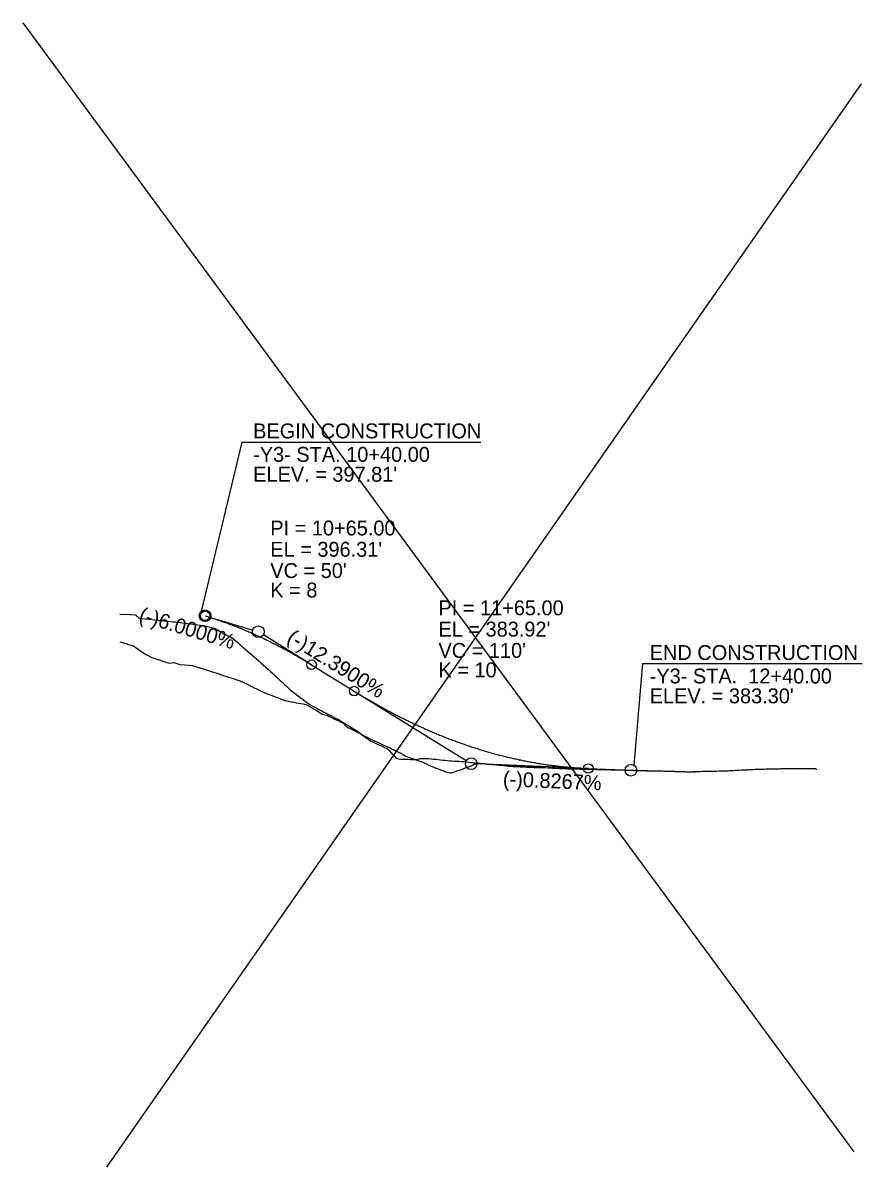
# Model space of a CAD drawing. Extents: x 1625686 to 1640492, y 1161393 to 1175642.
# Drawn here: x 1631145 to 1631540, y 1164721 to 1165258 of the extents above; entities that cross this region are included whole.
import ezdxf

# ---------------------------------------------------------------- set-up
doc = ezdxf.new("R2010")
doc.units = 0
for name, color, linetype in [('Exist Vertical Profile Ground Line', 7, 'Continuous'), ('Prop Vertical Profile Curve Label', 7, 'Continuous'), ('Prop Vertical Profile Grade', 7, 'Continuous'), ('Prop Vertical Profile Grade Label', 7, 'Continuous'), ('Prop VPI Label', 7, 'Continuous'), ('Scratch_Level_1', 7, 'Continuous'), ('Scratch_Level_3', 7, 'Continuous')]:
    doc.layers.add(name, color=color, linetype=linetype)

msp = doc.modelspace()

# ---------------------------------------------------------------- linework, layer by layer
at = {"layer": 'Exist Vertical Profile Ground Line'}
msp.add_lwpolyline([(1631191.04, 1164980.42), (1631195.96, 1164980.3), (1631198.27, 1164980.2), (1631200.18, 1164978.4), (1631201.29, 1164978.45), (1631216.18, 1164976.93), (1631216.75, 1164976.86), (1631217.11, 1164976.82), (1631231, 1164974.96), (1631235.41, 1164973.97), (1631240.72, 1164970.82), (1631241.99, 1164970.19), (1631243.08, 1164969.65), (1631243.96, 1164969.22), (1631245.27, 1164968.07), (1631246.37, 1164967.11), (1631247.46, 1164966.15), (1631248.56, 1164965.19), (1631249.65, 1164964.23), (1631250.75, 1164963.28), (1631251.84, 1164962.32), (1631253.01, 1164961.31), (1631254.03, 1164960.41), (1631255.12, 1164959.45), (1631256.22, 1164958.49), (1631257.31, 1164957.53), (1631258.41, 1164956.58), (1631259.5, 1164955.61), (1631260.6, 1164954.58), (1631261.69, 1164953.56), (1631262.79, 1164952.55), (1631263.88, 1164951.53), (1631264.98, 1164950.52), (1631266.07, 1164949.51), (1631267.17, 1164948.5), (1631268.26, 1164947.49), (1631269.36, 1164946.49), (1631270.45, 1164945.49), (1631271.55, 1164944.48), (1631272.64, 1164943.65), (1631273.74, 1164942.82), (1631274.83, 1164941.99), (1631275.93, 1164941.16), (1631277.02, 1164940.33), (1631278.11, 1164939.51), (1631279.21, 1164938.69), (1631280.3, 1164937.88), (1631281.4, 1164937.31), (1631282.49, 1164936.74), (1631283.59, 1164936.18), (1631284.68, 1164935.62), (1631285.78, 1164935.05), (1631286.87, 1164934.49), (1631287.97, 1164933.93), (1631289.06, 1164933.37), (1631290.16, 1164932.82), (1631291.25, 1164932.26), (1631292.35, 1164931.7), (1631293.44, 1164931.14), (1631294.54, 1164930.48), (1631295.63, 1164929.82), (1631296.73, 1164929.15), (1631297.82, 1164928.49), (1631298.91, 1164927.82), (1631300.01, 1164927.15), (1631301.1, 1164926.48), (1631302.2, 1164925.8), (1631303.29, 1164924.99), (1631304.39, 1164924.17), (1631305.48, 1164923.36), (1631306.58, 1164922.54), (1631307.67, 1164921.73), (1631308.76, 1164920.93), (1631309.86, 1164920.44), (1631310.95, 1164919.94), (1631312.05, 1164919.44), (1631313.14, 1164918.94), (1631314.24, 1164918.43), (1631315.33, 1164917.92), (1631316.71, 1164917.28), (1631317.52, 1164916.41), (1631318.62, 1164915.22), (1631319.71, 1164914.04), (1631320.8, 1164912.89), (1631321.9, 1164912.59), (1631322.99, 1164912.34), (1631324.09, 1164912.33), (1631325.18, 1164912.31), (1631326.28, 1164912.3), (1631327.37, 1164912.28), (1631328.47, 1164912.26), (1631329.56, 1164912.26), (1631330.65, 1164912.41), (1631331.75, 1164912.55), (1631332.18, 1164912.61), (1631332.84, 1164912.62), (1631333.94, 1164912.64), (1631335.03, 1164912.66), (1631335.57, 1164912.67), (1631336.13, 1164912.61), (1631337.22, 1164912.51), (1631338.32, 1164912.4), (1631339.41, 1164912.3), (1631340.51, 1164912.19), (1631341.6, 1164912.08), (1631342.69, 1164911.97), (1631343.79, 1164911.86), (1631344.88, 1164911.75), (1631345.98, 1164911.64), (1631347.07, 1164911.53), (1631348.17, 1164911.48), (1631349.26, 1164911.42), (1631350.36, 1164911.37), (1631351.45, 1164911.31), (1631352.55, 1164911.25), (1631353.64, 1164911.18), (1631354.73, 1164911), (1631355.83, 1164910.83), (1631356.49, 1164910.73), (1631356.92, 1164910.69), (1631358.02, 1164910.59), (1631359.11, 1164910.49), (1631360.22, 1164910.39), (1631361.3, 1164910.29), (1631362.4, 1164910.19), (1631363.49, 1164910.09), (1631364.58, 1164909.99), (1631365.01, 1164909.95), (1631365.68, 1164909.9), (1631366.77, 1164909.8), (1631367.87, 1164909.71), (1631368.96, 1164909.61), (1631370.06, 1164909.52), (1631371.15, 1164909.42), (1631372.25, 1164909.32), (1631372.85, 1164909.27), (1631373.41, 1164909.32), (1631374.44, 1164909.4), (1631375.69, 1164909.48), (1631376.62, 1164909.38), (1631377.72, 1164909.27), (1631378.81, 1164909.17), (1631379.91, 1164909.11), (1631381, 1164909.05), (1631382.1, 1164908.99), (1631382.74, 1164908.95), (1631383.19, 1164908.92), (1631384.29, 1164908.86), (1631385.38, 1164908.79), (1631386.47, 1164908.72), (1631387.57, 1164908.65), (1631388.66, 1164908.58), (1631389.76, 1164908.51), (1631390.85, 1164908.44), (1631391.95, 1164908.37), (1631393.04, 1164908.3), (1631394.14, 1164908.22), (1631395.23, 1164908.15), (1631396.33, 1164908.08), (1631397.42, 1164908), (1631398.2, 1164907.95), (1631398.51, 1164907.95), (1631399.61, 1164907.93), (1631400.7, 1164907.92), (1631401.8, 1164907.9), (1631402.95, 1164907.89), (1631403.99, 1164907.85), (1631405.08, 1164907.8), (1631406.18, 1164907.76), (1631407.42, 1164907.71), (1631408.37, 1164907.7), (1631409.46, 1164907.69), (1631410.55, 1164907.68), (1631411.65, 1164907.67), (1631412.74, 1164907.65), (1631413.84, 1164907.64), (1631414.93, 1164907.62), (1631416.03, 1164907.6), (1631417.12, 1164907.58), (1631418.22, 1164907.56), (1631419.31, 1164907.54), (1631420.4, 1164907.52), (1631421.5, 1164907.49), (1631422.59, 1164907.47), (1631423.69, 1164907.44), (1631424.78, 1164907.41), (1631425.88, 1164907.38), (1631426.97, 1164907.35), (1631428.7, 1164907.3), (1631433.57, 1164907.19), (1631444.01, 1164906.87), (1631444.87, 1164906.85), (1631445.72, 1164906.82), (1631446.58, 1164906.79), (1631447.44, 1164906.77), (1631448.3, 1164906.74), (1631449.15, 1164906.71), (1631450.01, 1164906.69), (1631450.87, 1164906.66), (1631451.73, 1164906.63), (1631452.59, 1164906.6), (1631453.67, 1164906.57), (1631454.3, 1164906.56), (1631455.16, 1164906.51), (1631456.02, 1164906.51), (1631456.49, 1164906.51), (1631456.87, 1164906.49), (1631457.73, 1164906.48), (1631458.59, 1164906.46), (1631459.45, 1164906.45), (1631460.31, 1164906.45), (1631460.62, 1164906.45), (1631461.16, 1164906.49), (1631462.02, 1164906.56), (1631462.88, 1164906.6), (1631463.74, 1164906.64), (1631464.63, 1164906.68), (1631465.45, 1164906.68), (1631466.31, 1164906.67), (1631467.18, 1164906.66), (1631468.03, 1164906.7), (1631468.5, 1164906.72), (1631468.88, 1164906.73), (1631469.79, 1164906.74), (1631470.6, 1164906.77), (1631471.46, 1164906.8), (1631472.55, 1164906.83), (1631473.26, 1164906.85), (1631474.03, 1164906.85), (1631474.95, 1164906.86), (1631475.75, 1164906.88), (1631476.73, 1164906.91), (1631477.51, 1164906.98), (1631478.32, 1164907.04), (1631478.87, 1164907.08), (1631479.18, 1164907.11), (1631480.05, 1164907.19), (1631481.04, 1164907.22), (1631481.75, 1164907.25), (1631482.61, 1164907.3), (1631483.47, 1164907.32), (1631484.6, 1164907.36), (1631485.18, 1164907.38), (1631486.04, 1164907.42), (1631486.9, 1164907.46), (1631487.76, 1164907.5), (1631488.61, 1164907.55), (1631489.47, 1164907.6), (1631490.33, 1164907.64), (1631491.19, 1164907.67), (1631492.05, 1164907.69), (1631492.9, 1164907.72), (1631493.76, 1164907.74), (1631494.62, 1164907.76), (1631495.48, 1164907.78), (1631496.33, 1164907.8), (1631497.19, 1164907.81), (1631497.62, 1164907.82), (1631498.05, 1164907.83), (1631498.91, 1164907.85), (1631499.77, 1164907.87), (1631500.12, 1164907.88), (1631500.76, 1164907.89), (1631501.48, 1164907.91), (1631502.62, 1164907.92), (1631503.2, 1164907.93), (1631504.06, 1164907.93), (1631505.13, 1164907.94), (1631505.77, 1164907.94), (1631506.63, 1164907.94), (1631507.65, 1164907.94), (1631508.34, 1164907.95), (1631509.3, 1164907.96), (1631510.18, 1164907.98), (1631510.92, 1164908), (1631511.39, 1164908.01), (1631511.78, 1164908.01), (1631512.71, 1164908.02), (1631513.49, 1164908.02), (1631514.53, 1164908.03), (1631515.26, 1164908.03), (1631516.06, 1164908.03), (1631516.92, 1164908.04), (1631517.83, 1164908.04)], dxfattribs=at)
at = {"layer": 'Prop Vertical Profile Curve Label'}
for centre in [(1631231.04, 1164979.72), (1631281.04, 1164956.74), (1631301.04, 1164944.35), (1631411.04, 1164908)]:
    msp.add_circle(centre, 2.25, dxfattribs=at)
at = {"layer": 'Prop Vertical Profile Grade'}
for p, q in [((1631281.04, 1164956.74), (1631301.04, 1164944.35)), ((1631411.04, 1164908), (1631431.04, 1164907.17))]:
    msp.add_line(p, q, dxfattribs=at)
for points in [[(1631231.04, 1164979.72), (1631232.04, 1164979.42), (1631233.04, 1164979.11), (1631234.04, 1164978.8), (1631235.04, 1164978.47), (1631236.04, 1164978.14), (1631237.04, 1164977.81), (1631238.04, 1164977.47), (1631239.04, 1164977.12), (1631240.04, 1164976.77), (1631241.04, 1164976.4), (1631242.04, 1164976.04), (1631243.04, 1164975.66), (1631244.04, 1164975.28), (1631245.04, 1164974.9), (1631246.04, 1164974.51), (1631247.04, 1164974.11), (1631248.04, 1164973.7), (1631249.04, 1164973.29), (1631250.04, 1164972.87), (1631251.04, 1164972.45), (1631252.04, 1164972.02), (1631253.04, 1164971.58), (1631254.04, 1164971.13), (1631255.04, 1164970.68), (1631256.04, 1164970.23), (1631257.04, 1164969.76), (1631258.04, 1164969.3), (1631259.04, 1164968.82), (1631260.04, 1164968.34), (1631261.04, 1164967.85), (1631262.04, 1164967.35), (1631263.04, 1164966.85), (1631264.04, 1164966.34), (1631265.04, 1164965.83), (1631266.04, 1164965.31), (1631267.04, 1164964.78), (1631268.04, 1164964.25), (1631269.04, 1164963.71), (1631270.04, 1164963.16), (1631271.04, 1164962.61), (1631272.04, 1164962.05), (1631273.04, 1164961.49), (1631274.04, 1164960.92), (1631275.04, 1164960.34), (1631276.04, 1164959.75), (1631277.04, 1164959.16), (1631278.04, 1164958.57), (1631279.04, 1164957.96), (1631280.04, 1164957.35), (1631281.04, 1164956.74)], [(1631301.04, 1164944.35), (1631303.24, 1164943), (1631305.44, 1164941.67), (1631307.64, 1164940.37), (1631309.84, 1164939.1), (1631312.04, 1164937.85), (1631314.24, 1164936.63), (1631316.44, 1164935.43), (1631318.64, 1164934.26), (1631320.84, 1164933.11), (1631323.04, 1164931.99), (1631325.24, 1164930.89), (1631327.44, 1164929.82), (1631329.64, 1164928.78), (1631331.84, 1164927.76), (1631334.04, 1164926.77), (1631336.24, 1164925.8), (1631338.44, 1164924.85), (1631340.64, 1164923.94), (1631342.84, 1164923.04), (1631345.04, 1164922.18), (1631347.24, 1164921.34), (1631349.44, 1164920.52), (1631351.64, 1164919.73), (1631353.84, 1164918.96), (1631356.04, 1164918.22), (1631358.24, 1164917.51), (1631360.44, 1164916.82), (1631362.64, 1164916.16), (1631364.84, 1164915.52), (1631367.04, 1164914.91), (1631369.24, 1164914.32), (1631371.44, 1164913.76), (1631373.64, 1164913.22), (1631375.84, 1164912.71), (1631378.04, 1164912.23), (1631380.24, 1164911.77), (1631382.44, 1164911.33), (1631384.64, 1164910.92), (1631386.84, 1164910.54), (1631389.04, 1164910.18), (1631391.24, 1164909.85), (1631393.44, 1164909.54), (1631395.64, 1164909.26), (1631397.84, 1164909), (1631400.04, 1164908.77), (1631402.24, 1164908.57), (1631404.44, 1164908.39), (1631406.64, 1164908.23), (1631408.84, 1164908.1), (1631411.04, 1164908)]]:
    msp.add_spline(points, degree=3, dxfattribs=at)
at = {"layer": 'Prop Vertical Profile Grade Label'}
for p, q in [((1631248.27, 1165061.37), (1631229.23, 1164981.79)), ((1631248.27, 1165061.37), (1631360.47, 1165061.37)), ((1631436.54, 1164957.25), (1631432.4, 1164909.56)), ((1631436.54, 1164957.25), (1631539.64, 1164957.25))]:
    msp.add_line(p, q, dxfattribs=at)
at = {"layer": 'Prop VPI Label'}
for p, q in [((1631231.04, 1164979.72), (1631253.4, 1164973.01)), ((1631281.04, 1164956.74), (1631258.38, 1164970.78)), ((1631301.04, 1164944.35), (1631353.7, 1164911.72)), ((1631411.04, 1164908), (1631358.79, 1164910.16))]:
    msp.add_line(p, q, dxfattribs=at)
for centre in [(1631231.04, 1164979.72), (1631256.04, 1164972.22), (1631356.04, 1164910.27), (1631431.04, 1164907.17)]:
    msp.add_circle(centre, 2.75, dxfattribs=at)
at = {"layer": 'Scratch_Level_1'}
for points in [[(1631191.04, 1164967.45), (1631193.89, 1164966.67), (1631194.55, 1164966.46), (1631197.41, 1164965.58), (1631198.67, 1164964.74), (1631203.13, 1164961.59), (1631203.89, 1164961.21), (1631205.99, 1164960.19), (1631208.4, 1164959.35), (1631213.07, 1164957.76), (1631214.1, 1164957.53), (1631216.28, 1164957.76), (1631219.15, 1164956.9), (1631223.6, 1164956.47), (1631224.91, 1164956.33), (1631225.36, 1164956.23), (1631226.08, 1164956.02), (1631232.62, 1164953.96), (1631233.8, 1164953.61), (1631236, 1164952.86), (1631239.24, 1164951.82), (1631241.99, 1164950.93), (1631243.08, 1164950.58), (1631244.18, 1164950.22), (1631245.44, 1164949.81), (1631246.37, 1164949.49), (1631247.46, 1164949.11), (1631248.03, 1164948.92), (1631248.56, 1164948.66), (1631249.65, 1164948.12), (1631250.75, 1164947.58), (1631251.84, 1164947.03), (1631252.22, 1164946.84), (1631252.94, 1164946.49), (1631254.03, 1164945.95), (1631255.12, 1164945.41), (1631256.22, 1164944.87), (1631257.31, 1164944.32), (1631258.41, 1164943.79), (1631259.5, 1164943.38), (1631260.6, 1164942.97), (1631261.69, 1164942.55), (1631262.79, 1164942.13), (1631263.88, 1164941.72), (1631264.62, 1164941.43), (1631264.98, 1164941.29), (1631266.07, 1164940.84), (1631267.17, 1164940.4), (1631268.37, 1164939.9), (1631269.36, 1164939.72), (1631270.45, 1164939.52), (1631271.55, 1164939.32), (1631272.64, 1164939.12), (1631273.74, 1164938.91), (1631274.83, 1164938.71), (1631275.93, 1164938.5), (1631277.02, 1164938.31), (1631278.41, 1164938.07), (1631279.21, 1164937.6), (1631280.3, 1164936.95), (1631281.4, 1164936.31), (1631282.49, 1164935.67), (1631283.59, 1164935.02), (1631284.68, 1164934.38), (1631285.78, 1164933.73), (1631286.09, 1164933.54), (1631286.87, 1164933.34), (1631287.97, 1164933.05), (1631288.41, 1164932.93), (1631289.06, 1164932.61), (1631290.16, 1164932.08), (1631291.25, 1164931.55), (1631292.35, 1164931.02), (1631293.44, 1164930.5), (1631294.54, 1164929.97), (1631295.74, 1164929.39), (1631296.73, 1164928.56), (1631297.82, 1164927.63), (1631298.46, 1164927.08), (1631298.91, 1164926.88), (1631300.01, 1164926.41), (1631300.32, 1164926.27), (1631301.1, 1164925.86), (1631302.2, 1164925.28), (1631303.29, 1164924.7), (1631304.39, 1164924.12), (1631305.48, 1164923.54), (1631306.58, 1164922.97), (1631307.67, 1164922.39), (1631308.29, 1164922.07), (1631308.84, 1164921.81), (1631309.86, 1164921.33), (1631310.95, 1164920.82), (1631312.05, 1164920.31), (1631313.14, 1164919.81), (1631314.24, 1164919.32), (1631315.59, 1164918.71), (1631316.43, 1164918.31), (1631317.52, 1164917.79), (1631318.62, 1164917.26), (1631319.71, 1164916.74)], [(1631319.71, 1164916.74), (1631320.8, 1164916.22), (1631321.9, 1164915.69), (1631322.99, 1164915.15), (1631324.09, 1164914.49), (1631325.29, 1164913.77), (1631326.28, 1164913.42), (1631327.37, 1164913.03), (1631328.47, 1164912.65), (1631329.56, 1164912.26), (1631330.65, 1164911.87), (1631331.75, 1164911.48), (1631332.84, 1164911.1), (1631333.39, 1164910.93), (1631333.94, 1164910.65), (1631335.03, 1164910.11), (1631336.13, 1164909.58), (1631337.22, 1164909.05), (1631338.32, 1164908.63), (1631339.41, 1164908.21), (1631340.51, 1164907.8), (1631341.6, 1164907.38), (1631342.69, 1164906.97), (1631343.03, 1164906.85), (1631343.93, 1164906.47), (1631344.45, 1164906.32), (1631344.88, 1164906.24), (1631346.12, 1164906), (1631346.6, 1164905.91), (1631347.07, 1164906.08), (1631348.17, 1164906.47), (1631349.26, 1164906.84), (1631350.36, 1164907.2), (1631351, 1164907.41), (1631351.45, 1164907.58), (1631352.55, 1164907.99), (1631353.64, 1164908.39), (1631354.73, 1164908.77), (1631355.26, 1164908.95), (1631355.99, 1164909.21), (1631356.92, 1164909.69), (1631358.02, 1164910.24), (1631358.79, 1164910.62), (1631359.11, 1164910.59), (1631360.21, 1164910.48), (1631361.3, 1164910.37), (1631362.4, 1164910.26), (1631363.49, 1164910.14), (1631364.58, 1164910.03), (1631365.68, 1164909.92), (1631366.9, 1164909.79), (1631367.87, 1164909.7), (1631368.96, 1164909.6), (1631370.06, 1164909.49), (1631371.15, 1164909.38), (1631372.25, 1164909.27), (1631372.74, 1164909.22), (1631373.34, 1164909.16), (1631374.06, 1164909.08), (1631374.44, 1164909.06), (1631375.17, 1164909.02), (1631375.53, 1164909), (1631376.62, 1164908.93), (1631377.3, 1164908.89), (1631377.72, 1164908.86), (1631378.98, 1164908.77), (1631379.91, 1164908.76), (1631381.24, 1164908.72), (1631382.1, 1164908.69), (1631382.77, 1164908.66), (1631383.19, 1164908.64), (1631383.82, 1164908.61), (1631384.29, 1164908.59), (1631385.63, 1164908.53), (1631386.47, 1164908.53), (1631387.65, 1164908.47), (1631388.66, 1164908.45), (1631389.03, 1164908.44), (1631389.76, 1164908.4), (1631390.85, 1164908.38), (1631391.95, 1164908.35), (1631393.04, 1164908.31), (1631394.29, 1164908.26), (1631395.23, 1164908.24), (1631395.7, 1164908.22), (1631396.33, 1164908.2), (1631396.95, 1164908.17), (1631397.42, 1164908.16), (1631398.51, 1164908.13), (1631399.08, 1164908.11), (1631399.62, 1164908.1), (1631400.7, 1164908.05), (1631401.4, 1164908.01), (1631401.8, 1164908.01), (1631402.31, 1164908), (1631402.89, 1164907.97), (1631403.31, 1164907.95), (1631403.99, 1164907.94), (1631405.22, 1164907.89), (1631405.68, 1164907.9), (1631406.18, 1164907.88)], [(1631406.18, 1164907.88), (1631407.27, 1164907.85), (1631407.75, 1164907.83), (1631408.37, 1164907.79), (1631409.01, 1164907.74), (1631409.46, 1164907.77), (1631410.55, 1164907.83), (1631410.89, 1164907.82), (1631411.68, 1164907.79), (1631412.76, 1164907.67), (1631413.29, 1164907.67), (1631413.84, 1164907.62), (1631414.62, 1164907.55), (1631414.93, 1164907.56), (1631416.09, 1164907.58), (1631416.48, 1164907.56), (1631417.21, 1164907.56), (1631418.22, 1164907.48), (1631418.92, 1164907.42), (1631419.31, 1164907.43), (1631420.4, 1164907.45), (1631420.99, 1164907.46), (1631421.78, 1164907.43), (1631422.59, 1164907.41), (1631423.69, 1164907.37), (1631424.78, 1164907.33), (1631425.88, 1164907.33), (1631427.6, 1164907.31), (1631429.29, 1164907.11), (1631430.54, 1164907.16), (1631432.03, 1164907.12), (1631432.93, 1164907.02), (1631433.47, 1164907.05), (1631434.74, 1164906.95), (1631436.8, 1164907.06), (1631438.38, 1164906.91), (1631439.35, 1164906.95), (1631440.19, 1164906.91), (1631441.57, 1164906.96), (1631442.28, 1164906.94), (1631443.43, 1164906.93), (1631444.01, 1164906.9), (1631444.87, 1164906.87), (1631445.21, 1164906.85), (1631445.72, 1164906.84), (1631446.58, 1164906.81), (1631447.48, 1164906.72), (1631448.3, 1164906.72), (1631449.32, 1164906.65), (1631450.01, 1164906.68), (1631450.94, 1164906.72), (1631451.73, 1164906.69), (1631452.59, 1164906.62), (1631453.03, 1164906.59), (1631453.73, 1164906.57), (1631454.3, 1164906.54), (1631455.16, 1164906.51), (1631456.02, 1164906.51), (1631456.49, 1164906.51), (1631456.87, 1164906.5), (1631457.73, 1164906.49), (1631458.59, 1164906.46), (1631459.45, 1164906.46), (1631460.41, 1164906.52), (1631461.16, 1164906.53), (1631462.02, 1164906.55), (1631462.56, 1164906.57), (1631462.88, 1164906.59), (1631463.74, 1164906.64), (1631464.63, 1164906.68), (1631465.45, 1164906.68), (1631466.31, 1164906.67), (1631467.18, 1164906.66), (1631468.03, 1164906.7), (1631468.5, 1164906.72), (1631468.88, 1164906.73), (1631469.79, 1164906.74), (1631470.6, 1164906.77), (1631471.46, 1164906.8), (1631472.55, 1164906.83), (1631473.25, 1164906.85), (1631474.03, 1164906.85), (1631474.95, 1164906.86), (1631475.75, 1164906.91), (1631476.6, 1164906.95), (1631477.51, 1164906.98), (1631478.32, 1164907.05), (1631478.65, 1164907.08), (1631479.18, 1164907.12), (1631480.05, 1164907.19), (1631481.04, 1164907.22), (1631481.75, 1164907.25), (1631482.61, 1164907.3), (1631483.47, 1164907.32), (1631484.33, 1164907.35), (1631485.18, 1164907.38), (1631485.49, 1164907.39), (1631486.04, 1164907.42), (1631486.9, 1164907.46), (1631487.78, 1164907.51), (1631488.61, 1164907.55)], [(1631488.61, 1164907.55), (1631489.47, 1164907.6), (1631490.33, 1164907.64), (1631491.19, 1164907.67), (1631492.05, 1164907.69), (1631492.9, 1164907.72), (1631493.76, 1164907.74), (1631494.62, 1164907.76), (1631495.48, 1164907.78), (1631496.33, 1164907.8), (1631497.19, 1164907.81), (1631497.74, 1164907.82), (1631498.05, 1164907.83), (1631498.91, 1164907.85), (1631499.77, 1164907.87), (1631500.15, 1164907.88), (1631500.76, 1164907.9), (1631501.48, 1164907.91), (1631502.76, 1164907.92), (1631503.2, 1164907.93), (1631504.06, 1164907.93), (1631505.13, 1164907.94), (1631505.77, 1164907.94), (1631506.63, 1164907.94), (1631507.65, 1164907.94), (1631508.4, 1164907.95), (1631509.2, 1164907.96), (1631510.18, 1164907.98), (1631510.92, 1164908), (1631511.39, 1164908.01), (1631511.78, 1164908.01), (1631512.71, 1164908.02), (1631513.49, 1164908.02), (1631514.53, 1164908.03), (1631515.26, 1164908.03), (1631516.06, 1164908.03), (1631516.92, 1164908.04), (1631517.83, 1164908.04), (1631518.11, 1164907.3)]]:
    msp.add_lwpolyline(points, dxfattribs=at)
at = {"layer": 'Scratch_Level_3'}
for p, q in [((1631145.43, 1165258.27), (1631535.82, 1164727.88)), ((1631184.83, 1164720.72), (1631539.41, 1165229.6))]:
    msp.add_line(p, q, dxfattribs=at)

# ---------------------------------------------------------------- texts
at = {"layer": 'Prop Vertical Profile Curve Label'}
for s, p in [("VC = 50'", (1631261.65, 1164997.47)), ('K = 8', (1631261.65, 1164988.33)), ("VC = 110'", (1631340.65, 1164959.96)), ('K = 10', (1631340.65, 1164950.81))]:
    msp.add_text(s, height=7, dxfattribs=at).set_placement(p)
at = {"layer": 'Prop Vertical Profile Grade Label'}
for s, rotation, p in [('(-)6.0000%', 343.3008, (1631199.46, 1164977.24)), ('(-)12.3900%', 328.2218, (1631268.9, 1164967.78)), ('(-)0.8267%', 357.6331, (1631370.81, 1164899.65))]:
    msp.add_text(s, height=7, rotation=rotation, dxfattribs=at).set_placement(p)
at = {"layer": 'Prop VPI Label'}
for s, p in [('BEGIN CONSTRUCTION', (1631253.6, 1165063.08)), ('-Y3- STA. 10+40.00', (1631253.6, 1165052.05)), ("ELEV. = 397.81'", (1631253.6, 1165042.73)), ('PI = 10+65.00', (1631261.65, 1165017.47)), ("EL = 396.31'", (1631261.65, 1165007.47)), ('PI = 11+65.00', (1631340.65, 1164979.96)), ("EL = 383.92'", (1631340.65, 1164969.96)), ('END CONSTRUCTION', (1631439.87, 1164958.97)), ('-Y3- STA.  12+40.00', (1631439.87, 1164947.93)), ("ELEV. = 383.30'", (1631439.87, 1164938.61))]:
    msp.add_text(s, height=7, dxfattribs=at).set_placement(p)

doc.saveas('drawing.dxf')
